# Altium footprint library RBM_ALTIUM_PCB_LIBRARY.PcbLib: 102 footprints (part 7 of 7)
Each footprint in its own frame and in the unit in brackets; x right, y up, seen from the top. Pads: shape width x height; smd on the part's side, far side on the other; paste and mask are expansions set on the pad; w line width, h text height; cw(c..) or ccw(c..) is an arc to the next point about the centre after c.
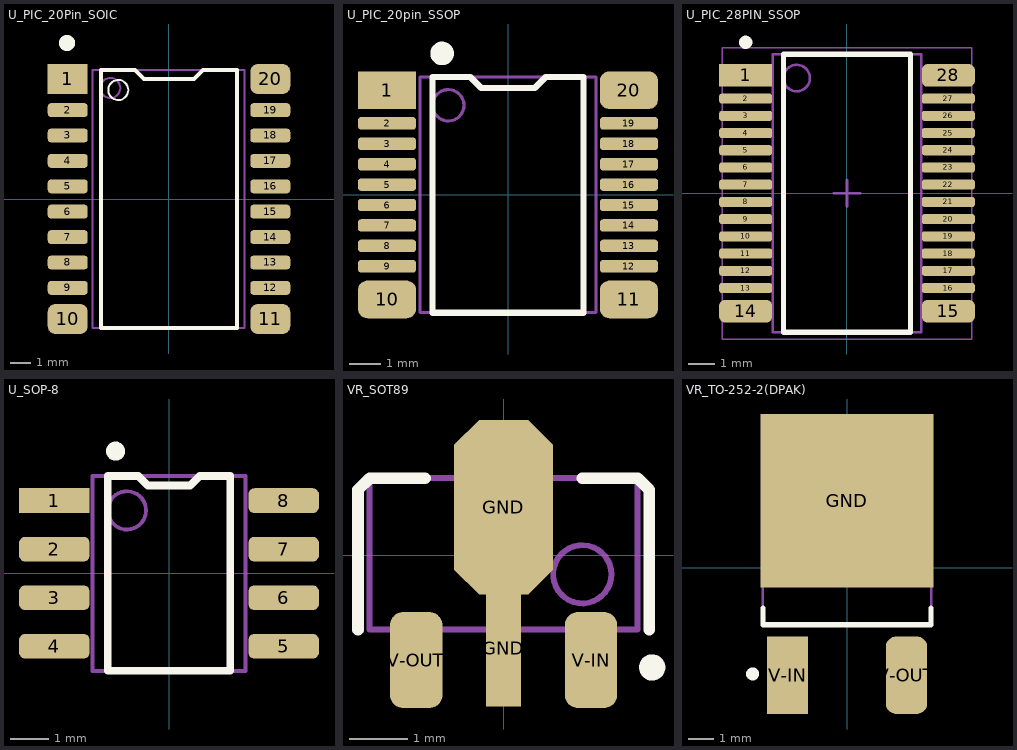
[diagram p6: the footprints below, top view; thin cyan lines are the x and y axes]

## U_PIC_20Pin_SOIC [mm] "SOIC, 20-Leads, Body 12.80x7.50mm, Pitch 1.27mm, IPC Medium Density"
height 2.65
pads (20):
  rect 2x1.5 smd mask+0.3: 1(-5.063,6)
  rrect50% 2x0.7 smd mask+0.3: 2(-5.063,4.445) 3(-5.063,3.175) 4(-5.063,1.905) 5(-5.063,0.635) 6(-5.063,-0.635) 7(-5.063,-1.905) 8(-5.063,-3.175) 9(-5.063,-4.445) 12(5.063,-4.445) 13(5.063,-3.175) 14(5.063,-1.905) 15(5.063,-0.635) 16(5.063,0.635) 17(5.063,1.905) 18(5.063,3.175) 19(5.063,4.445)
  rrect50% 2x1.5 smd mask+0.3: 10(-5.063,-6) 11(5.063,-6)
  rrect50% 2x1.5 smd paste+0 mask+0.3: 20(5.063,6)
Top Overlay:
  circle w0.4: c-5.1,7.8 r0.2
  circle w0.1: c-2.537,5.45 r0.5
  lines w0.2: -3.4,-6.45 -3.4,6.45 -1.7,6.45 -1.25,6 1.25,6 1.7,6.45 3.4,6.45 3.4,-6.45 -3.4,-6.45
Mechanical 13:
  circle w0.1: c-2.937,5.55 r0.5
  lines w0.1: -3.837,-6.45 -3.837,6.45 3.763,6.45 3.763,-6.45 -3.837,-6.45
3D body "SOIC127P1020X265-20N.step": height 2.65, standoff 0, extent -5.062,-6.425 5.088,6.475

## U_PIC_20pin_SSOP [mm] "SOP, 20-Leads, Body 7.20x5.30mm, Pitch 0.65mm, IPC Medium Density"
height 2
pads (20):
  rect 1.85x1.2 smd mask+0.2: 1(-3.85,3.33)
  rrect50% 1.85x0.395 smd mask+0.2: 2(-3.85,2.275) 3(-3.85,1.625) 4(-3.85,0.975) 5(-3.85,0.325) 6(-3.85,-0.325) 7(-3.85,-0.975) 8(-3.85,-1.625) 9(-3.85,-2.275) 12(3.85,-2.275) 13(3.85,-1.625) 14(3.85,-0.975) 15(3.85,-0.325) 16(3.85,0.325) 17(3.85,0.975) 18(3.85,1.625) 19(3.85,2.275)
  rrect50% 1.85x1.2 smd mask+0.2: 10(-3.85,-3.33) 11(3.85,-3.33) 20(3.85,3.33)
Top Overlay:
  circle w0.5: c-2.1,4.5 r0.125
  lines w0.2: -2.4,-3.75 2.4,-3.75 2.4,3.75 1.2,3.75 0.85,3.4 -0.85,3.4 -1.2,3.75 -2.4,3.75 -2.4,-3.75
Mechanical 13:
  circle w0.1: c-1.9,2.85 r0.5
  lines w0.1: -2.8,-3.75 2.8,-3.75 2.8,3.75 -2.8,3.75 -2.8,-3.75
3D body "SOP65P780X200-20N.step": height 2, standoff 0, extent -3.9,-3.75 3.9,3.75

## U_PIC_28PIN_SSOP [mm] "SOP, 28-Leads, Body 10.20x5.30mm, Pitch 0.65mm, Thermal Pad 8.00x4.00mm, IPC Medium Density"
height 2
pads (28):
  rect 2x0.85 smd mask+0.2: 1(-3.825,4.45)
  rrect50% 2x0.38 smd mask+0.2: 2(-3.825,3.575) 3(-3.825,2.925) 4(-3.825,2.275) 5(-3.825,1.625) 6(-3.825,0.975) 7(-3.825,0.325) 8(-3.825,-0.325) 9(-3.825,-0.975) 10(-3.825,-1.625) 11(-3.825,-2.275) 12(-3.825,-2.925) 13(-3.825,-3.575) 16(3.825,-3.575) 17(3.825,-2.925) 18(3.825,-2.275) 19(3.825,-1.625) 20(3.825,-0.975) 21(3.825,-0.325) 22(3.825,0.325) 23(3.825,0.975) 24(3.825,1.625) 25(3.825,2.275) 26(3.825,2.925) 27(3.825,3.575)
  rrect50% 2x0.85 smd mask+0.2: 14(-3.825,-4.45) 15(3.825,-4.45) 28(3.825,4.45)
Top Overlay:
  circle w0.25: c-3.825,5.7 r0.125
  lines w0.2: -2.4,-5.25 2.4,-5.25 2.4,5.25 -2.4,5.25 -2.4,-5.25
Assembly Top:
  circle w0.1: c-1.9,4.35 r0.5
  lines w0.1: -2.8,-5.25 2.8,-5.25 2.8,5.25 -2.8,5.25 -2.8,-5.25
Courtyard Top:
  lines w0.05: -4.7,-5.5 4.7,-5.5 4.7,5.5 -4.7,5.5 -4.7,-5.5
  lines w0.1: -0.5,0 0.5,0 ; 0,-0.5 0,0.5
3D body "U_PIC16F18856_SSOP.step": height 2, standoff 0, extent -3.9,-5.25 3.9,5.25

## U_SOP-8 [mm] "OB2225M"
height 1.75
pads (8):
  rect 1.85x0.65 smd mask+0.4: 1(-3,1.905)
  rrect50% 1.85x0.65 smd mask+0.4: 2(-3,0.635) 3(-3,-0.635) 4(-3,-1.905) 5(3,-1.905) 6(3,-0.635) 7(3,0.635) 8(3,1.905)
Top Overlay:
  circle w0.25: c-1.4,3.2 r0.125
  lines w0.2: -1.6,-2.55 -1.6,2.55 -0.8,2.55 -0.55,2.3 0.55,2.3 0.8,2.55 1.6,2.55 1.6,-2.55 -1.6,-2.55
Assembly Top:
  circle w0.1: c-1.1,1.65 r0.5
  lines w0.1: -2,-2.55 -2,2.55 2,2.55 2,-2.55 -2,-2.55
3D body "SOP127P600X175_HS-9N.step": height 1.75, standoff 0, extent -3,-2.55 3,2.55

## VR_SOT89 [mm] "SOT89, 3-Leads, Body 4.50x2.45mm, Pitch 1.50mm, Lead Span 4.1mm - Reverse Pinning, IPC Medium Density"
height 1.6
pads (4):
  rect 0.6x2 smd: GND(0,-1.6)
  oct 1.7x3 smd: GND(0,0.823)
  rrect50% 0.9x1.65 smd: V-IN(1.5,-1.8) V-OUT(-1.5,-1.8)
Top Overlay:
  circle w0.25: c2.55,-1.927 r0.1
  lines w0.2: -2.5,-1.277 -2.5,1.123 -2.3,1.323 -1.35,1.323 ; 1.35,1.323 2.3,1.323 2.5,1.123 2.5,-1.277
Mechanical 13:
  circle w0.1: c1.35,-0.327 r0.5
  lines w0.1: -2.3,-1.277 2.3,-1.277 2.3,1.323 -2.3,1.323 -2.3,-1.277
3D body "SOT89R-150P410X160-3N.step": height 1.6, standoff 0, extent -2.3,-2.2 2.3,1.8

## VR_TO-252-2(DPAK) [mm] "D-PAK, 3-Pads, Body 6.20x6.61mm (max), IPC Medium Density"
height 2.4
pads (3):
  rect 6.7x6.7 smd: GND(0,2.6)
  rect 1.6x3 smd: V-IN(-2.3,-4.15)
  rrect50% 1.6x3 smd: V-OUT(2.3,-4.15)
Top Overlay:
  circle w0.25: c-3.65,-4.1 r0.125
  lines w0.2: -3.25,-1.55 -3.25,-2.2 3.25,-2.2 3.25,-1.55
Mechanical 13:
  lines w0.1: -3.25,-2.2 3.25,-2.2 3.25,4 -3.25,4 -3.25,-2.2
3D body "ST7805.step": height 2.5, standoff 0, extent -3.25,-4.275 3.25,5.45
